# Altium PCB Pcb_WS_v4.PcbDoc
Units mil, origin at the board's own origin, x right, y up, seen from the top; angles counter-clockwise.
Board outline 3937.01 x 3937.01 mil, 2 copper layers (Top Layer, Bottom Layer); 75 components, 61 nets, 248 pads, 32 vias.
Unrouted connection lines stored in the file: 190.
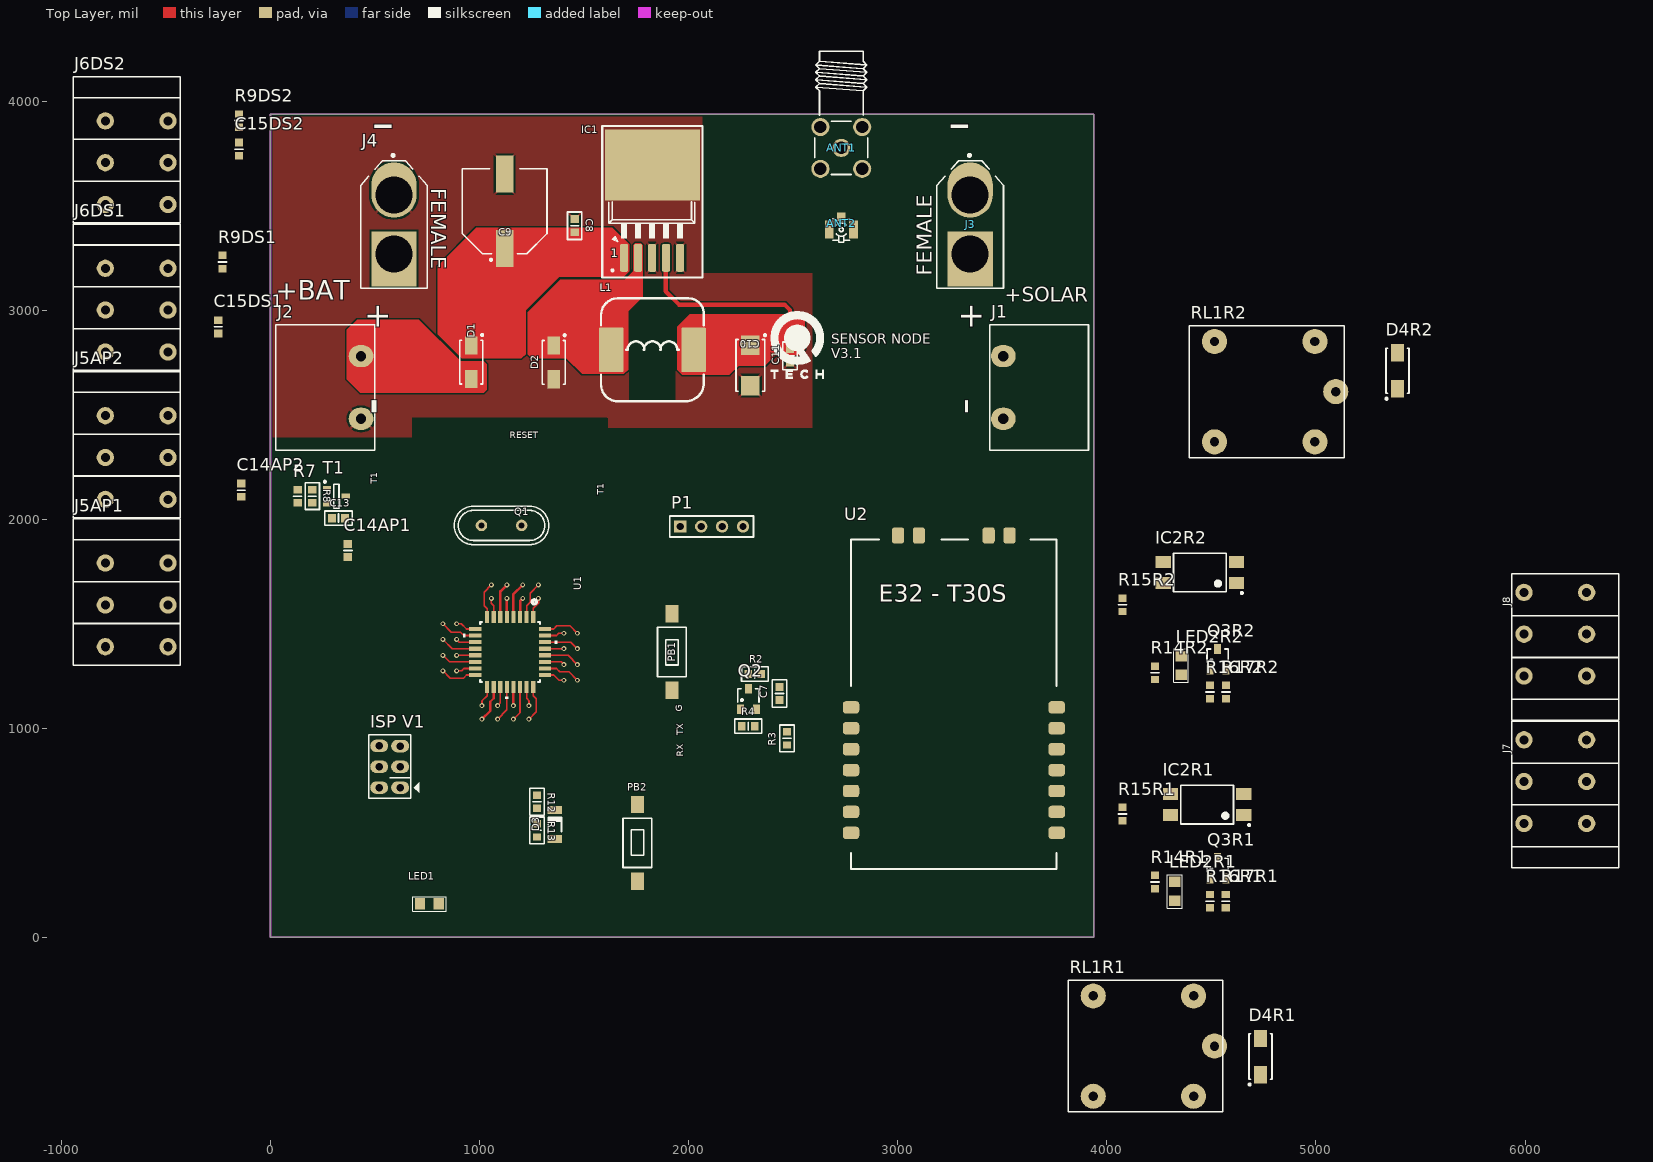
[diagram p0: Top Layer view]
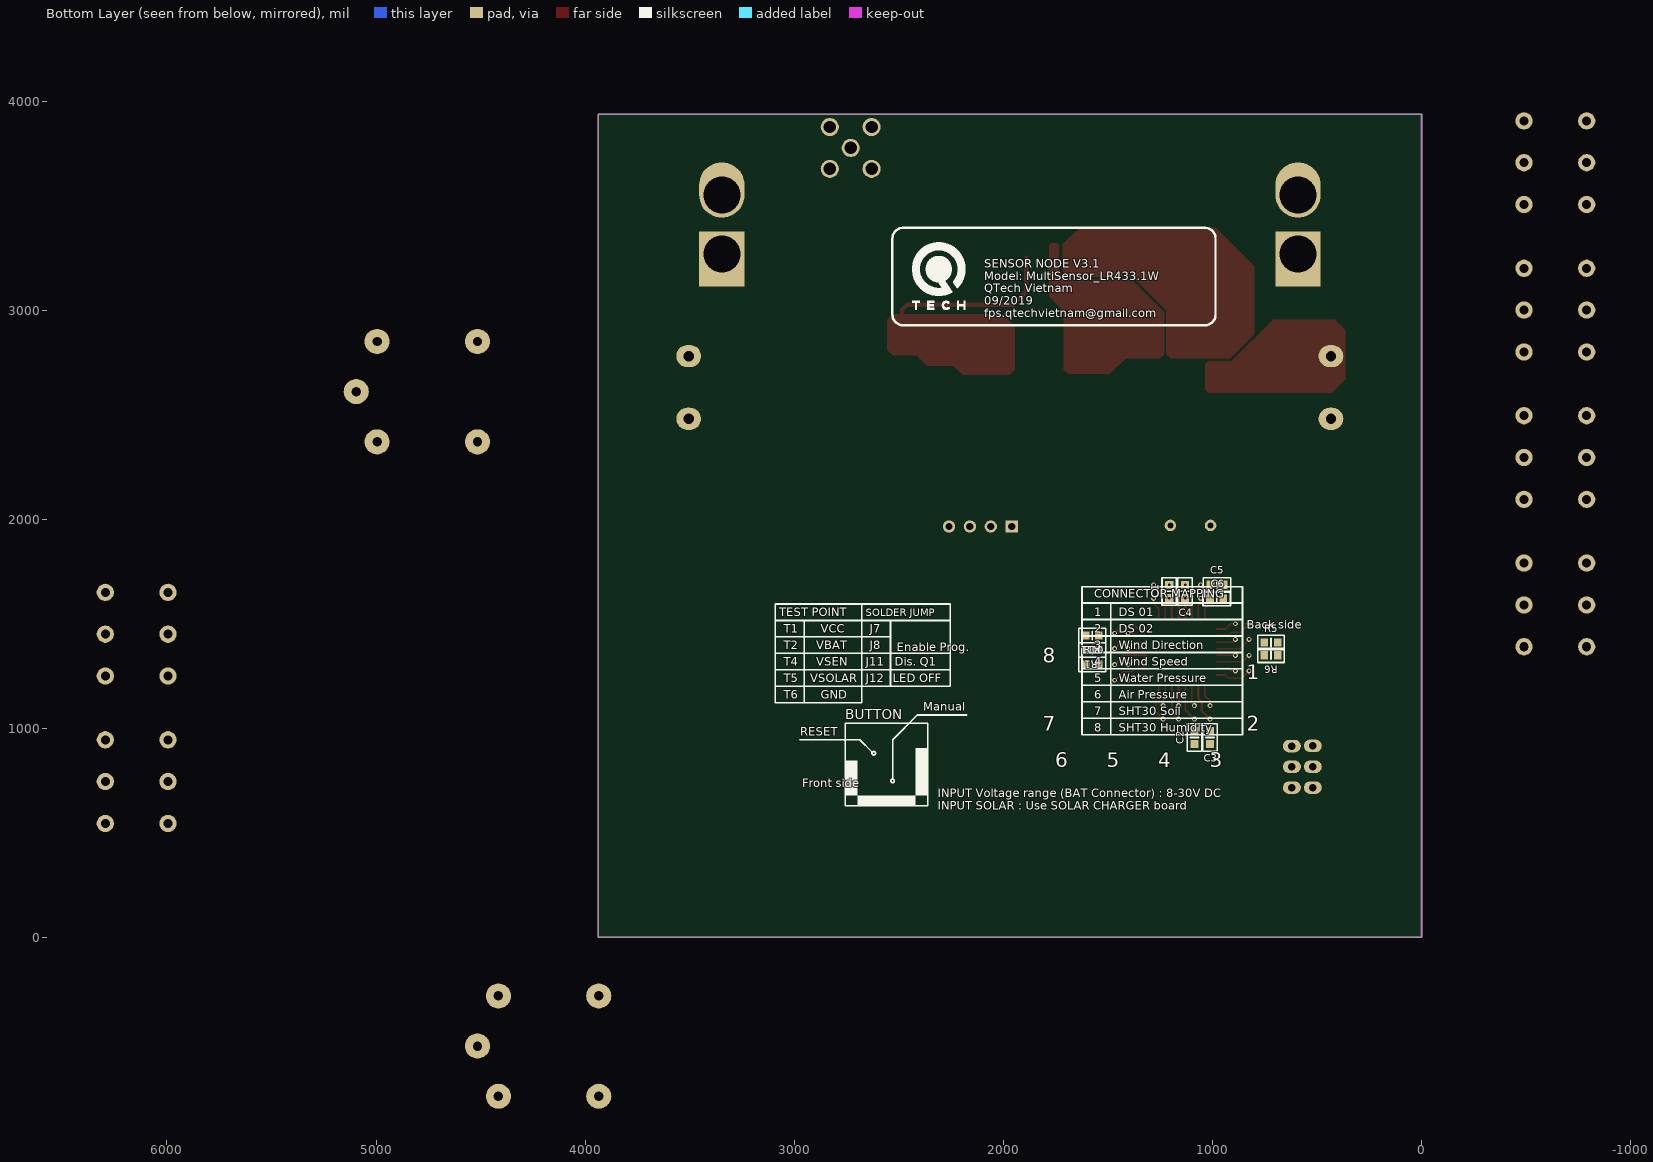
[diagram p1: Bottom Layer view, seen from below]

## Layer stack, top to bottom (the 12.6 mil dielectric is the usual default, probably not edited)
Top Solder: solder mask 0.4, Solder Resist, Dk 3.5
Top Layer: signal copper 1.4
Dielectric 1: dielectric 12.6, FR-4, Dk 4.8
Bottom Layer: signal copper 1.4
Bottom Solder: solder mask 0.4, Solder Resist, Dk 3.5

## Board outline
0,0 0,3937.01 3937.01,3937.01 3937.01,0

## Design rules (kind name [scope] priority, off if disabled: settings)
Clearance [All] p1: gap=7 ignorepadtopadclearanceinfootprint=FALSE
ComponentClearance KF-conn_Clearance [InComponentClass('KF_conn') vs InComponentClass('KF_conn')] p1: gap=5 collisioncheckmode=3 verticalgap=0 showdistances=FALSE
ComponentClearance HS_Comp_Clearance [InComponentClass('HS_Comp')] p2: gap=175 collisioncheckmode=3 verticalgap=100 showdistances=FALSE
ComponentClearance IC_Comp_Clearance [InComponentClass('IC_Comp') And OnLayer('Top Layer') vs IsComponent And OnLayer('Top Layer')] p3: gap=150 collisioncheckmode=3 verticalgap=100 showdistances=FALSE
ComponentClearance conn-th_Clearance [InComponentClass('conn-th')] p4: gap=150 collisioncheckmode=3 verticalgap=250 showdistances=FALSE
ComponentClearance chip-ge_Clearance [InComponentClass('chip-ge')] p5: gap=100 collisioncheckmode=3 verticalgap=50 showdistances=FALSE
ComponentClearance chip-0603_Clearance [InComponentClass('chip-0603')] p6: gap=15 collisioncheckmode=3 verticalgap=10 showdistances=FALSE
PolygonConnect [All] p1: thpad.connectstyle=Relief thpad.reliefconductorwidth=13.78 thpad.reliefentries=4 thpad.polygonreliefangle="45 Angle" thpad.airgapwidth=10 smdpad.connectstyle=Relief smdpad.reliefconductorwidth=11.81 smdpad.reliefentries=4 smdpad.polygonreliefangle="45 Angle" smdpad.airgapwidth=10 via.connectstyle=Direct via.reliefconductorwidth=10 via.reliefentries=4 via.polygonreliefangle="90 Angle" via.airgapwidth=10
RoutingVias [All] p1: holewidth=11.81 width=23.62 viastyle="Through Hole" minholewidth=11.81 minwidth=23.62 maxholewidth=11.81 maxwidth=23.62
ShortCircuit [All] p1: allowed=TRUE
SolderMaskExpansion [All] p1: expansion=4 istentingtop=FALSE
Width [All] p1: maxlimit=196.85 minlimit=8 preferedwidth=8
28 further rules are at their usual default settings.

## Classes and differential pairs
component class KF_conn: J5AP1 J5AP2 J6DS1 J6DS2 J7 J8
component class HS_Comp: ANT1 ANT2 Q1
component class IC_Comp: IC1 IC2R1 IC2R2 L1 U1 U2
component class chip-ge: C9 C10 D1 D2 D4R1 D4R2
component class conn-th: "ISP V1" J1 J2 J3 J4 J5AP1 J5AP2 J6DS1 J6DS2 J7 J8 P1 PB1 PB2 RL1R2
component class chip-0603: C1 C2 C3 C4 C5 C6 C7 C8 C11 C13 C14AP1 C14AP2 C15DS1 C15DS2 D3 LED1 LED2R1 LED2R2 Q2 Q3R1 Q3R2 R1 R2 R3 R4 R5 R6 R7 R8 R9DS1 R9DS2 R10 R11 R12 R13 R14R1 R14R2 R15R1 R15R2 R16R1 R16R2 R17R1 R17R2 T1
channel class Sensor_DS18b20_1Wire: DS1 DS2
channel class Sensor_AirPressure_1Wire: AP1 AP2
channel class Relay: R1 R2
component class Top_Level: D3 J7 J8 LED1 P1 PB2 R10 R11 R12 R13
component class R2: D4R2 IC2R2 LED2R2 Q3R2 R14R2 R15R2 R16R2 R17R2 RL1R2
component class R1: D4R1 IC2R1 LED2R1 Q3R1 R14R1 R15R1 R16R1 R17R1
component class Main: C1 C2 C3 C4 C5 C6 "ISP V1" PB1 Q1 R1 U1
component class Lora: ANT1 ANT2 C7 Q2 R2 R3 R4 R5 R6 U2
component class DS2: C15DS2 J6DS2 R9DS2
component class DS1: C15DS1 J6DS1 R9DS1
component class AP2: C14AP2 J5AP2
component class AP1: C14AP1 J5AP1
component class PWR: C8 C9 C10 C11 C13 D1 D2 IC1 J1 J2 J3 J4 L1 R7 R8 T1

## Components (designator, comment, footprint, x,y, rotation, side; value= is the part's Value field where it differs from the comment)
ANT1 "Coax_1Female_1Shield" "HUBER-SUHNER_85 SMA-50-0-101/111 NE" 2729.98,3775.65 r90 top
ANT2 "U.FL" HIROSE_U.FL-R-SMT-1(10) 2729.98,3385 r180 top
C1 "100nF" CAPC1608X87N 1206.61,1654.72 r270 bottom
C2 "100nF" CAPC1608X87N 1086.21,955.57 r90 bottom
C3 "100nF" CAPC1608X87N 1011.21,955.57 r270 bottom
C4 "100nF" CAPC1608X87N 1130.66,1654.72 r270 bottom
C5 "100nF" CAPC1608X87N 978.46,1686.21 r180 bottom value=22pF
C6 "100nF" CAPC1608X87N 979.41,1621.21 r180 bottom value=22pF
C7 "100nF" CAPC1608X87N 2435,1166.5 r270 top
C8 "100nF" CAPC1608X87N 1455,3403.5 r90 top
C9 "470uF" CAPAE1030X1020N 1120,3472.83 r90 top
C10 "100uF" CAPMP6032X280N 2295,2735.24 r270 top
C11 "100nF" CAPC1608X87N 2485,2781.5 r270 top
C13 "100nF" CAPC1608X87N 325,2005.04 r180 top
C14AP1 "100nF" CAPC1608X87N 370,1850 r90 top (schematic designator C14)
C14AP2 "100nF" CAPC1608X87N -140,2138.5 r90 top (schematic designator C14)
C15DS1 "100nF" CAPC1608X87N -250,2920 r90 top (schematic designator C15)
C15DS2 "100nF" CAPC1608X87N -150,3770 r90 top (schematic designator C15)
D1 "SS16" DIOM5127X229N 960,2750.71 r270 top
D2 "SS16" DIOM5127X229N 1355,2750 r270 top
D3 "BZV55-B5V1" DIOMELF3515N 1360,540 r270 top
D4R1 "BZG03C220" DIOM5326X230N 4735,-570 r90 top (schematic designator D4)
D4R2 "BZG03C220" DIOM5326X230N 5390,2710 r90 top (schematic designator D4)
IC1 "LM2596" TO263-5 1691.14,3250 r0 top
IC2R1 "SFH6156-4" SOIC254P977X406-4N 4480,635 r180 top (schematic designator IC2)
IC2R2 "SFH6156-4" SOIC254P977X406-4N 4445,1745 r180 top (schematic designator IC2)
"ISP V1" "Connector 3x2" JP3x2 570,816 r90 top
J1 "CON KF7.62-2P" "CON KF7.62-2P" 3505,2630 r270 top
J2 "CON KF7.62-2P" "CON KF7.62-2P" 433.07,2630 r90 top
J3 "XT60-FM" XT60-FM 3346.46,3409.45 r270 top locked
J4 "XT60-FM" XT60-FM 590.55,3409.45 r270 top locked
J5AP1 "KF142V-3P" "CON KF142V-3P-5.08" -490,1390 r90 top (schematic designator J5)
J5AP2 "KF142V-3P" "CON KF142V-3P-5.08" -490,2095 r90 top (schematic designator J5)
J6DS1 "KF142V-3P" "CON KF142V-3P-5.08" -490,2800 r90 top (schematic designator J6)
J6DS2 "KF142V-3P" "CON KF142V-3P-5.08" -490,3505 r90 top (schematic designator J6)
J7 "KF142V-3P" "CON KF142V-3P-5.08" 5995,945 r270 top
J8 "KF142V-3P" "CON KF142V-3P-5.08" 5995,1650 r270 top
L1 "33uH" L_SMD 1630,2810 r90 top
LED1 "LED" L-0805 760,160 r180 top value="LED 3 ly Single Colour"
LED2R1 "LED" L-0805 4325,220 r90 top value="LED 3 ly Single Colour" (schematic designator LED2)
LED2R2 "LED" L-0805 4355,1300 r90 top value="LED 3 ly Single Colour" (schematic designator LED2)
P1 "Header 4" HDR1X4 1960,1965 r0 top
PB1 "Push Button" PB_TYCO_FSMSM 1920,1365 r270 top
PB2 "Push Button" PB_TYCO_FSMSM 1755,451.93 r90 top
Q1 "20MHz" XTAL_HC-49/U 1105,1970 r0 top
Q2 "C1815" SOT23-3 2285,1140 r0 top
Q3R1 "C1815" SOT23-3 4530,330 r0 top (schematic designator Q3)
Q3R2 "C1815" SOT23-3 4530,1330 r0 top (schematic designator Q3)
R1 "10k" RESC1608X55N 1575,1375 r180 bottom
R2 "10k" RESC1608X55N 2316.5,1260 r0 top value=4k7
R3 "10k" RESC1608X55N 2470,951.5 r90 top value=1k
R4 "10k" RESC1608X55N 2285,1010 r180 top value=1k
R5 "4k7" RESC1608X55N 720,1410 r180 bottom value=10k
R6 "4k7" RESC1608X55N 720,1349.06 r180 bottom value=10k
R7 "1k" RESC1608X55N 130,2110 r90 top
R8 "10k" RESC1608X55N 200,2110 r90 top
R9DS1 "4k7" RESC1608X55N -230,3230 r90 top (schematic designator R9)
R9DS2 "4k7" RESC1608X55N -150,3906.5 r90 top (schematic designator R9)
R10 "10k" RESC1608X55N 1575,1304.61 r0 bottom value=200
R11 "10k" RESC1608X55N 1575,1443.54 r180 bottom
R12 "10k" RESC1608X55N 1275,648.5 r270 top value=2M
R13 "10k" RESC1608X55N 1275,511.5 r270 top value=1M
R14R1 "1k" RESC1608X55N 4230,265 r90 top value=200 (schematic designator R14)
R14R2 "1k" RESC1608X55N 4230,1265 r90 top value=200 (schematic designator R14)
R15R1 "1k" RESC1608X55N 4075,590 r270 top (schematic designator R15)
R15R2 "1k" RESC1608X55N 4075,1590 r270 top (schematic designator R15)
R16R1 "1k" RESC1608X55N 4493,173.5 r90 top value=200 (schematic designator R16)
R16R2 "1k" RESC1608X55N 4493,1173.5 r90 top value=200 (schematic designator R16)
R17R1 "10k" RESC1608X55N 4568.8,173.5 r270 top (schematic designator R17)
R17R2 "10k" RESC1608X55N 4570.2,1173.5 r90 top (schematic designator R17)
RL1R1 "Relay 10A/12V" RL_SPDT_10A 4515,-520 r180 top value="Relay SPDT, 10A, 12V" (schematic designator RL1)
RL1R2 "Relay 10A/12V" RL_SPDT_10A 5095,2610 r180 top value="Relay SPDT, 10A, 12V" (schematic designator RL1)
T1 "BSH203" SOT95P230X110-3N 315,2110 r0 top
U1 "ATmega328-AU" 32A_ATM-M 1146.41,1364.8 r270 top locked
U2 "E32-T30S" E32-T30S 3760,1902.36 r180 top

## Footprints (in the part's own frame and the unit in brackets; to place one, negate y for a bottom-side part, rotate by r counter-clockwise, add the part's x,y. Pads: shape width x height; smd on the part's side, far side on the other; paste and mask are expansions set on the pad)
32A_ATM-M [mil]
  rect 58x20 smd paste+0 mask+5: 1(-167,110.24) 2(-167,78.74) 3(-167,47.24) 4(-167,15.75) 5(-167,-15.75) 6(-167,-47.24) 7(-167,-78.74) 8(-167,-110.24) 17(167,-110.24) 18(167,-78.74) 19(167,-47.24) 20(167,-15.75) 21(167,15.75) 22(167,47.24) 23(167,78.74) 24(167,110.24)
  rect 20x58 smd paste+0 mask+5: 9(-110.24,-167) 10(-78.74,-167) 11(-47.24,-167) 12(-15.75,-167) 13(15.75,-167) 14(47.24,-167) 15(78.74,-167) 16(110.24,-167) 25(110.24,167) 26(78.74,167) 27(47.24,167) 28(15.75,167) 29(-15.75,167) 30(-47.24,167) 31(-78.74,167) 32(-110.24,167)
  silkscreen extent -250,-224 224,224, body extent -182,-182 182,182, height 47
CAPAE1030X1020N [mm] "Capacitor, Aluminium Electrolytric, 10.3mm L X 10.3mm W X 10.2mm H, IPC Medium Density"
  rect 4.5x2.1 smd: 1(-4.5,0) 2(4.5,0)
  silkscreen extent -6.02,-5.15 5.15,5.15, body extent -6,-5.25 6,5.25, height 10.2
CAPC1608X87N [mm] "Chip Capacitor, Body 1.6x0.8mm IPC Medium Density"
  rect 0.95x1 smd: 1(-0.8,0) 2(0.8,0)
  silkscreen extent -1.68,-0.87 1.68,0.87, body extent -0.87,-0.47 0.88,0.48, height 0.87
CAPMP6032X280N [mm] "Capacitor, Polarized, Molded  Body 6.0x3.2mm, IPC Medium Density"
  rect 2.35x2.25 smd: 1(-2.45,0) 2(2.45,0)
  silkscreen extent -3.8,-1.75 3.15,1.9, body extent -3.15,-1.75 3.15,1.75, height 2.8
"CON KF7.62-2P" [mm]
  oval 2.7x3 hole 1.26: 1(-3.81,0) 2(3.81,0)
  silkscreen extent -7.62,-1.65 7.62,10.35, body extent -7.62,-1.65 7.62,10.35, height 12.4
"CON KF142V-3P-5.08" [mm]
  round 2.1 hole 1.1: 1(0,7.62) 1(0,0) 2(5.08,7.62) 2(5.08,0) 3(10.16,0) 3(10.16,7.62)
  silkscreen extent -2.25,-1.5 15.53,11.5, body extent -2.14,-1.57 15.54,11.63, height 14.23
DIOM5127X229N [mm] "DO-214-AC/SMA Molded Diode, 2-Leads, Body 5.1x2.7mm, IPC Medium Density"
  rect 2.2x1.55 smd: 1(-2.05,0) 2(2.05,0)
  silkscreen extent -3.42,-1.4 2.65,1.45, body extent -2.67,-1.45 2.68,1.45, height 2.29
DIOM5326X230N [mm] "DO-214-AC/SMA Molded Diode, Body 5.3x2.6mm, IPC Medium Density"
  rect 2.1x1.55 smd: 1(-2.2,0) 2(2.2,0)
  silkscreen extent -3.52,-1.4 2.75,1.45, body extent -2.75,-1.4 2.75,1.4, height 2.3
DIOMELF3515N [mm] "SOD80C, MELF Diode, 2-Leads, Body 3.5x1.5mm, IPC Medium Density"
  rect 1x1.75 smd: 1(-1.75,0) 2(1.75,0)
  silkscreen extent -0.85,-0.8 0.85,0.8, body extent -1.85,-0.8 1.85,0.8, height 1.6
E32-T30S [mm] "Lora-EBYTE-21~30dBm-UART-SX1278-25x40mm"
  rrect50% 2x1.5 smd: 1(0,20.38) 2(0,22.92) 3(0,25.46) 4(0,28) 5(0,30.54) 6(0,33.08) 7(0,35.62) 8(24.98,35.62) 9(24.98,33.08) 10(24.98,30.54) 11(24.98,28) 12(24.98,25.46) 13(24.98,22.92) 14(24.98,20.38)
  rrect50% 1.5x2 smd: 15(19.27,-0.5) 16(16.73,-0.5) 17(8.27,-0.5) 18(5.73,-0.5)
  silkscreen extent 0,0 25,40, body extent 0,0 25,40, height 3.5
HDR1X4 [mm] "Connector; Header; 4 Position"
  rect 1.5x1.5 hole 0.9: 1(0,0)
  round 1.5 hole 0.9: 2(2.54,0) 3(5.08,0) 4(7.62,0)
  silkscreen extent -1.27,-1.27 8.89,1.27
HIROSE_U.FL-R-SMT-1(10) [mm] "Up to 6GHz Ultra Small Surface Mount Male Coaxial Connectors U.FL Series"
  rect 1x1.05 smd: 1(0,-1.525)
  rect 1.05x2.2 smd: 2(-1.475,0) 2(1.475,0)
  silkscreen extent -1,-1.3 1,1.55, body extent -1.5,-1.55 1.5,1.55, height 1.25
"HUBER-SUHNER_85 SMA-50-0-101/111 NE" [mm] "50 Ohm SMA Right Angle PCB Jack"
  round 2.2 hole 1.5: 1(0,0) 2(-2.54,-2.54) 2(-2.54,2.54) 2(2.54,-2.54) 2(2.54,2.54)
  silkscreen extent -3.23,-3.23 11.73,3.23, body extent -3.23,-3.23 11.73,3.23, height 9.6
JP3x2 [mil] "Connector 3x2"
  oval 60x86 hole 36: 1(-100,-50) 2(0,-50) 3(99,-50) 4(-100,50) 5(0,50) 6(100,50)
  silkscreen extent -150,-141 154,100, body extent -150,-100 150,100, height 335
L-0805 [mil] "Compoment SMD 80x50mil"
  rect 50x55 smd: 1(-45,0) 2(45,0)
  silkscreen extent -80,-35 80,35, body extent -50,-20 50,20, height 43
L_SMD [mm]
  rrect10% 5.4x3 smd mask+0.1: 1(0,0) 2(0,-10)
  silkscreen extent -6.25,-11.25 6.25,1.25, body extent -6.25,-11.25 6.25,1.25, height 6.7
PB_TYCO_FSMSM [mm] "Body 3.5x6.0mm, Pushbutton Switch,  TYCO FSMSM Serie"
  rect 2.1x1.6 smd: 1(-4.65,0) 2(4.65,0)
  silkscreen extent -3,-1.75 3,1.75, body extent -5,-1.75 5,1.75, height 4.3
RESC1608X55N [mm] "Chip Resistor, EIA 0603, Metric 1608, Body 1.6x0.8mm, IPC Medium Density"
  rect 0.9x1 smd: 1(-0.8,0) 2(0.8,0)
  silkscreen extent -1.63,-0.87 1.63,0.87, body extent -0.87,-0.47 0.88,0.48, height 0.55
RL_SPDT_10A [mil] "Relay SPDT, 5 pin, 10A,W 650mil, L 800mil, H 800mil"
  round 120 hole 45: 1(0,0) 2(580,240) 3(580,-240) 4(100,-240) 5(100,240)
  silkscreen extent -40,-315 700,315
SOIC254P977X406-4N [mm] "SOIC, 2.54mm pitch; 4 pin, 6.65mm W X 4.69mm L, IPC Medium Density"
  rect 1.85x1.45 smd: 1(-4.45,1.27) 2(-4.45,-1.27) 3(4.45,-1.27) 4(4.45,1.27)
  silkscreen extent -5.23,-2.35 3.2,2.62, body extent -5.01,-2.41 5.02,2.42, height 4.06
SOT23-3 [mm] "SOT 23"
  rect 0.85x1.2 smd: 1(-0.94,-1.245) 2(0.985,-1.25) 3(0.005,1.25)
  silkscreen extent -1.29,-0.38 1.31,1.25, body extent -1.5,-1.5 1.52,1.5, height 1.27
SOT95P230X110-3N [mm] "SOT23, 3 pin, Pitch 0.95mm - 1.3mm W X 2.9mm L X 1.1mm H, IPC Medium Density"
  rect 1x0.6 smd: 1(-1.15,0.95) 2(-1.15,-0.95) 3(1.15,0)
  silkscreen extent -1.52,-1.45 0.33,1.87, body extent -1.17,-1.5 1.33,1.5, height 1.1
TO263-5 [mm]
  rrect50% 1x3.4 smd: 1(0,0) 2(1.7,0) 4(5.1,0) 5(6.8,0)
  rrect50% 1x3.4 smd mask+0: 3(3.4,0)
  rect 11.5x8.634 smd: 6(3.45,11.302)
  silkscreen extent -2.66,-2.38 9.54,16.02, body extent -1.71,-0.87 8.45,13.77, height 4.57
XT60-FM [mm]
  oval 6.716x5.516 hole 4.5 copper offset -0.6,0: 1(-3.6,0)
  rect 6.716x5.516 hole 4.5 copper offset 0.6,0: 2(3.6,0)
  silkscreen extent -8.55,-4.05 7.75,4.05, body extent -7.81,-4.07 8.12,4.06, height 15.5
XTAL_HC-49/U [mm] "HC-49/U Leaded Cristal, Body 11.05x4.8mm; Pitch 4.88mm"
  round 1.4 hole 0.7: 1(-2.44,0) 2(2.44,0)
  silkscreen extent -5.75,-2.33 5.75,2.33, body extent -5.75,-2.33 5.75,2.33, height 3.5

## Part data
ANT1: library part HUBER-SUHNER_85_SMA-50-0-101/111_NE, Manufacturer=HUBER+SUHNER, Manufacturer Part Number=85_SMA-50-0-101/111_NE
ANT2: library part HIROSE_U.FL-R-SMT-1(10), Manufacturer="HIROSE (HRS)", Manufacturer Part Number=U.FL-R-SMT-1(10)
C1 C2 C3 C4 C7 C8 C11 C13 C14AP1 C14AP2 C15DS1 C15DS2: library part CC0603_100NF_50V_10%_X7R, "Non-polarised capacitor", Case=0603, Manufacturer=GENERIC, Manufacturer1 ComponentHeight=0.87mm, Manufacturer1 Example=PHYCOMP, Manufacturer1 Part Number=223858615649, Tolerance=±10%, Voltage=50V
C5 C6: library part CC0603_22PF_50V_5%_NP0, "Non-polarised capacitor", Case=0603, Manufacturer=GENERIC, Manufacturer1 ComponentHeight=0.87mm, Manufacturer1 Example=PHYCOMP, Manufacturer1 Part Number=223886715229, Tolerance=±5%, Voltage=50V
C9: library part CAE1030-1020_470UF_25V_20%, "Polarised capacitor", Case=G, Manufacturer=GENERIC, Manufacturer1 ComponentHeight=10.2mm, Manufacturer1 Example=PANASONIC, Manufacturer1 Part Number=EEEFK1E471AP, Tolerance=±20%, Voltage=25V
C10: library part CTE6032-28_100UF_6.3V_10%_LESR0075, "Polarised capacitor", Case=C, Manufacturer=GENERIC, Manufacturer1 ComponentHeight=2.8mm, Manufacturer1 Example=AVX, Manufacturer1 Part Number=TPSC107K006R0075, Tolerance=±10%, Voltage=6.3V
D1 D2: "Schottky Diode", Case=DO-214AC, Manufacturer="VISHAY GENERAL SEMICONDUCTOR", Power=1A, Voltage=60V
D3: "Zener Diode", Case=SOD-80C, Manufacturer="NXP SEMICONDUCTORS", Power=500mW, Voltage=5V1
D4R1 D4R2: "Zener Diode", Case=DO-214AC, Manufacturer="VISHAY SEMICONDUCTOR", Power=1.25W, Voltage=220V
IC1: library part LM2596-5V
IC2R1 IC2R2: "Single Optocoupler", Case=SOIC4, Manufacturer="VISHAY SEMICONDUCTORS"
"ISP V1": library part JP3x2
J3 J4: Package="Package Analog Devices"
J5AP1 J5AP2 J6DS1 J6DS2 J7 J8: library part "CON KF142V-3P-5.08", "CON KF142V-3P-5.08"
L1: library part "L_SMD 33uH"
LED1 LED2R1 LED2R2: "LED Single colour Green and Red"
P1: "Header, 4-Pin"
PB1 PB2: "Push-Button Switch SPDT", Manufacturer="TYCO ELECTRONICS", Manufacturer Part Number="FSMSM or 1437566-3", Part Number=PB_TYCO_FSMSM
Q1: library part XTAL_20MHZ_AEL_HC-49/U, "Quartz Crystal", Manufacturer="AEL CRYSTALS", Manufacturer Part Number=X20M000000L010
Q2 Q3R1 Q3R2: library part 2SC1815, PSpiceTemplate="Q^@REFDES %c %b %e @MODEL"
R1 R5 R6 R8 R11 R17R1 R17R2: library part R0603_10K_1%_0.1W_100PPM, "Resistor - 1%", Case=0603, Manufacturer=GENERIC, Manufacturer1 ComponentHeight=0.55mm, Manufacturer1 Example="NIC COMPONENT", Manufacturer1 Part Number=NRC06F1002TRF, Power=0.1W, Tolerance=±1%
R2 R9DS1 R9DS2: library part R0603_4K7_1%_0.1W_100PPM, "Resistor - 1%", Case=0603, Manufacturer=GENERIC, Manufacturer1 ComponentHeight=0.55mm, Manufacturer1 Example="NIC COMPONENT", Manufacturer1 Part Number=NRC06F4701TRF, Power=0.1W, Tolerance=±1%
R3 R4 R7 R15R1 R15R2: library part R0603_1K_1%_0.1W_100PPM, "Resistor - 1%", Case=0603, Manufacturer=GENERIC, Manufacturer1 ComponentHeight=0.55mm, Manufacturer1 Example="NIC COMPONENT", Manufacturer1 Part Number=NRC06F1001TRF, Power=0.1W, Tolerance=±1%
R10 R14R1 R14R2 R16R1 R16R2: library part R0603_200R_1%_0.1W_100PPM, "Resistor - 1%", Case=0603, Manufacturer=GENERIC, Manufacturer1 ComponentHeight=0.55mm, Manufacturer1 Example="NIC COMPONENT", Manufacturer1 Part Number=NRC06F2000TRF, Power=0.1W, Tolerance=±1%
R12: library part R0603_2M_1%_0.1W_100PPM, "Resistor - 1%", Case=0603, Manufacturer=GENERIC, Manufacturer1 ComponentHeight=0.55mm, Manufacturer1 Example="NIC COMPONENT", Manufacturer1 Part Number=NRC06F2004TRF, Power=0.1W, Tolerance=±1%
R13: library part R0603_1M_1%_0.1W_100PPM, "Resistor - 1%", Case=0603, Manufacturer=GENERIC, Manufacturer1 ComponentHeight=0.55mm, Manufacturer1 Example="NIC COMPONENT", Manufacturer1 Part Number=NRC06F1004TRF, Power=0.1W, Tolerance=±1%
RL1R1 RL1R2: library part "Relay 1", "Relay SPDT,10A - 12VDC 5 Pin"
T1: "P-CHANNEL MOSFET WITH DIODE", Case=SOT23-3, Manufacturer="NXP SEMICONDUCTORS"
U1: "8-bit AVR Microcontroller, 32KB Flash, 1KB EEPROM, 2KB SRAM, 32-pin TQFP, Industrial Grade (-40°C to 85°C)", Supplier Part Number 1=ATMEGA328-AU-ND
U2: library part E32-433T30S, "Lora Ebyte E32-T30S Module"

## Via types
v1: diameter 23.62, hole 11.81, Top Layer to Bottom Layer, 32 vias

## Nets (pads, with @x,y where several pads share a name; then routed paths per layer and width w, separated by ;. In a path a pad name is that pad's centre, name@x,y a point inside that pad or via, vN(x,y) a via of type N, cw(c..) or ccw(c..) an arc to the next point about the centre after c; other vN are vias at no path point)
ANT_M: U2.18
ANT_M1: ANT1.1 ANT2.1
AREF: C2.2 U1.20 | length 172.8
  Top Layer w8: v1(1086.21,1043.39) 1130.66,1087.84 U1.20
AUX: U1.2 U2.5 | length 177.8
  Top Layer w8: U1.2 1225.15,1586.13 1241.61,1602.59 1241.61,1646.21 v1(1281.61,1686.21)
BAT-VSEN: C8.1 C9.1 D1.1 IC1.1 R12.1
BAT-VSEN-Q: D3.1 R12.2 R13.1 U1.23 | length 94
  Top Layer w8: U1.23 1225.15,1143.48 1236.21,1132.41 v1(1236.21,1108.39)
CLOSE1: J7.3 RL1R1.2
CLOSE2: J8.3 RL1R2.2
COM1: J7.2 RL1R1.1
COM2: J8.2 RL1R2.1
DATA-AP1: J5AP1.2 U1.24 | length 174.9
  Top Layer w8: v1(1236.21,1043.39) 1271.21,1078.39 1271.21,1141.39 1256.65,1155.96 U1.24
DATA-AP2: J5AP2.2 U1.25 | length 99.7
  Top Layer w8: U1.25 1355.25,1254.57 1380.21,1229.61 v1(1402.82,1229.61)
DATA-DS1: J6DS1.2 R9DS1.1 U1.1 | length 99.7
  Top Layer w8: U1.1 1256.65,1573.65 1281.61,1598.61 v1(1281.61,1621.21)
DATA-DS2: J6DS2.2 R9DS2.1 U1.9 | length 99.7
  Top Layer w8: v1(890,1500) 912.61,1500 937.57,1475.04 U1.9
GND: "ISP V1.5" ANT1.2 ANT2.2 C1.2 C2.1 C3.2 C4.2 C5.2 C6.2 C7.2 C8.2 C9.2 C10.2 C11.2 C13.2 C14AP1.1 C14AP2.1 C15DS1.1 C15DS2.1 D2.2 D3.2 IC1.3 IC1.5 IC1.6 IC2R1.2 IC2R2.2 J2.1 J4.1 J5AP1.3 J5AP2.3 J6DS1.3 J6DS2.3 LED1.2 P1.4 PB1.2 PB2.2 Q2.2 Q3R1.2 Q3R2.2 R4.1 R5.2 R6.2 R7.1 R13.2 R17R1.1 R17R2.1 U1.3 U1.5 U1.21 U2.7 U2.9 U2.15 U2.16 U2.17 | length 273.6
  Top Layer w12: U1.5 v1(1130.66,1621.21) ; v1(1162.16,1108.39) U1.21 ; U1.3 1193.65,1608.26 v1(1206.61,1621.21)
GND-SOLAR: J1.2 J3.1
LED: R10.1 U1.28 | length 172.8
  Top Layer w8: U1.28 1423.37,1349.06 v1(1467.82,1304.61)
M0: U1.11 U2.1 | length 94.8
  Top Layer w8: v1(890,1425) 902.95,1412.05 U1.11
M1: U1.12 U2.2 | length 172.8
  Top Layer w8: v1(825,1425) 869.45,1380.55 U1.12
MISO: "ISP V1.2" U1.16 | length 174.9
  Top Layer w8: v1(825,1275) 860,1240 923,1240 937.57,1254.57 U1.16
MOSI: "ISP V1.3" U1.15 | length 94
  Top Layer w8: v1(890,1275) 914.02,1275 925.08,1286.06 U1.15
NetD2_1: D2.1 IC1.2 L1.1
NetD4R1_2: D4R1.2 LED2R1.2 Q3R1.3 RL1R1.4
NetD4R2_2: D4R2.2 LED2R2.2 Q3R2.3 RL1R2.4
NetIC2R1_1: IC2R1.1 R15R1.2
NetIC2R2_1: IC2R2.1 R15R2.2
NetLED1_1: LED1.1 R10.2
NetLED2R1_1: LED2R1.1 R14R1.2
NetLED2R2_1: LED2R2.1 R14R2.2
NetQ2_1: Q2.1 R3.2
NetQ3R1_1: Q3R1.1 R16R1.2
NetQ3R2_1: Q3R2.1 R16R2.2
NetR7_2: R7.2 R8.2 T1.1
NetU1_19: U1.19 | length 94.8
  Top Layer w8: v1(1086.21,1108.39) 1099.17,1121.35 U1.19
NetU1_22: U1.22 | length 167.5
  Top Layer w8: v1(1162.16,1043.39) 1193.65,1074.89 U1.22
NetU2_10: U2.10
NetU2_11: U2.11
NetU2_12: U2.12
NetU2_13: U2.13
NetU2_14: U2.14
OPEN1: J7.1 RL1R1.3
OPEN2: J8.1 RL1R2.3
P5V-Main: "ISP V1.6" C1.1 C3.1 C4.1 C7.1 C10.1 C11.1 D4R1.1 D4R2.1 IC1.4 IC2R1.4 IC2R2.4 L1.2 P1.1 R1.1 R2.2 R8.1 R11.1 R14R1.1 R14R2.1 RL1R1.5 RL1R2.5 T1.2 U1.4 U1.6 U1.18 U2.6 | length 1497.4
  Top Layer w12: v1(1011.21,1043.39) 1051.21,1083.39 1051.21,1127.02 1067.67,1143.48 U1.18 ; U1.6 1099.17,1654.72 v1(1130.66,1686.21) ; U1.4 1162.16,1641.76 v1(1206.61,1686.21)
  Top Layer w20: IC1.4@1890,3250 1890,3090 1954.14,3025.86 2459.14,3025.86 2485,3000 C11.1
P5V-SEN: C13.1 C14AP1.2 C14AP2.2 C15DS1.2 C15DS2.2 J5AP1.1 J5AP2.1 J6DS1.1 J6DS2.1 R9DS1.2 R9DS2.2 T1.3
P12V-BAT: D1.2 J2.2 J4.2
P16V-SOLAR: J1.1 J3.2
RESET-E32: R3.1 R4.2 U1.10 | length 177.8
  Top Layer w8: v1(825,1500) 865,1460 908.62,1460 925.08,1443.54 U1.10
RL-CTL1: R15R1.1 U1.26 | length 177.8
  Top Layer w8: U1.26 1367.74,1286.06 1384.19,1269.61 1427.82,1269.61 v1(1467.82,1229.61)
RL-CTL2: R15R2.1 U1.27 | length 94.8
  Top Layer w8: U1.27 1389.87,1317.56 v1(1402.82,1304.61)
RL-CTR1: IC2R1.3 R16R1.1 R17R1.2
RL-CTR2: IC2R2.3 R16R2.1 R17R2.2
RST-E32: Q2.3 R2.1 U2.8
RST_MCU: "ISP V1.4" PB1.1 R1.2 U1.29 | length 89.4
  Top Layer w8: U1.29 v1(1402.82,1380.55)
RXD-E32: R6.1 U1.13 U2.3 | length 89.4
  Top Layer w8: v1(890,1349.06) U1.13
RXM: P1.3 U1.30 | length 167.5
  Top Layer w8: U1.30 1436.32,1412.05 v1(1467.82,1380.55)
SCK: "ISP V1.1" U1.17 | length 99.7
  Top Layer w8: v1(1011.21,1108.39) 1011.21,1131 1036.17,1155.96 U1.17
TXD-E32: R5.1 U1.14 U2.4 | length 167.5
  Top Layer w8: v1(825,1349.06) 856.5,1317.56 U1.14
TXM: P1.2 U1.31 | length 94
  Top Layer w8: U1.31 1367.74,1443.54 1378.8,1454.61 v1(1402.82,1454.61)
WAKE: PB2.1 R11.2 U1.32 | length 174.9
  Top Layer w8: U1.32 1355.25,1475.04 1369.82,1489.61 1432.82,1489.61 v1(1467.82,1454.61)
XTAL1: C6.1 Q1.1 U1.7 | length 94
  Top Layer w8: v1(1056.61,1621.21) 1056.61,1597.2 1067.67,1586.13 U1.7
XTAL2: C5.1 Q1.2 U1.8 | length 174.9
  Top Layer w8: U1.8 1036.17,1571.57 1021.61,1586.13 1021.61,1651.21 v1(1056.61,1686.21)

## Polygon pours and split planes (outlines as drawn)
GND on Top Layer "GND_L01_P027" (solid, remove dead copper, pour order 27): 0.04,2391.99 0.04,3936.99 2065.04,3936.99 2065.04,3176.99 2590.04,3176.99 2590.04,2436.99 1610.04,2436.99 1610.04,2486.99 675.04,2486.99 675.04,2391.99
no net on Top Layer "AutoNaming" (solid, pour order 26): 0,0
no net on Top Layer "AutoNaming" (solid, pour order 22): 0,0
no net on Top Layer "Top Layer-No Net" (solid, pour order 14): 1502.91,3276.41

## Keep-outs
Keep-Out Layer:
  the board outline again, w7.87

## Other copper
Top Layer:
  region net P5V-Main: 1945,2920 2005,2980 2530,2980 2555,2955 2555,2810 2530,2785 2415,2785 2365,2735 2240,2735 2195,2690 1970,2690 1945,2715
  region: 340,2910
  region net P12V-BAT: 365,2670 430,2605 1020,2605 1035,2620 1035,2740 1020,2755 910,2755 710,2955 415,2955 365,2905
  region net BAT-VSEN: 915,2770 800,2885 800,3210 985,3395 1635,3395 1715,3315 1715,3185 1690,3160 1380,3160 1220,3000 1220,2790 1200,2770
  region net NetD2_1: 1735,3185 1695,3145 1385,3145 1230,2990 1230,2790 1250,2770 1415,2770 1490,2695 1690,2695 1710,2715 1710,2995 1780,3065 1780,3310 1770,3320 1745,3320 1735,3310
  region: 1965,2640
  pour cut-out: 1787.5,3150 1882.5,3150 1882.5,3135 1787.5,3135
  pour cut-out: 3949.69,1440.41
  pour cut-out: 3949.69,1440.41
  region: 991.15,955.57
Multi-Layer:
  pour cut-out: 1715,3000 1715,2570 1935,2570 1935,3000
  pour cut-out: 0,2389 681.15,2389 681.15,2484 1615.34,2484 1615.34,2436.76 717.39,2436.76 717.39,2351 0,2351

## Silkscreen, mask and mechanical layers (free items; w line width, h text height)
Top Overlay:
  drawing of 802 lines, arcs and shapes, not listed
  text "-" at 482.28,3720.47 h393.7
  text "-" at 3238.19,3720.47 h393.7
  text "FEMALE" at 767.72,3582.48 h70.87 r270
  text "FEMALE" at 3162.72,3165.48 h70.87 r90
  text "+BAT" at 26,3018 h157.48
  text "+SOLAR" at 3511,3015 h118.11
  text "+" at 600.39,2904.11 h196.85 r90
  text "+" at 3438.98,2903.54 h196.85 r90
  text "SENSOR NODE / V3.1" at 2682.41,2769.24 h47.24
  text "-" at 600.39,2500 h275.59 r90
  text "-" at 610.24,2500 h275.59 r90
  text "-" at 3438.98,2500 h275.59 r90
  text "RESET" at 1145.39,2388.26 h31.5
  text "T1" at 511.83,2168.48 h31.5 r90
  text "T1" at 1594,2116.39 h31.5 r90
  text "G" at 1970.39,1078.39 h31.5 r90
  text "TX" at 1973.39,967.39 h31.5 r90
  text "RX" at 1973.39,863.39 h31.5 r90
Bottom Overlay:
  drawing of 873 lines, arcs and shapes, not listed
  text "SENSOR NODE V3.1 / Model: MultiSensor_LR433.1W / QTech Vietnam / 09/2019 / fps.qtechvietnam@gmail.com" at 2092.27,2966.11 h39.37
  text "CONNECTOR MAPPING" at 1565.09,1624.02 h39.37
  text "DS 01" at 1446.98,1535.43 h39.37
  text "1" at 1564.96,1535.43 h39.37
  text "SOLDER JUMP" at 2657.48,1535.43 h35.43
  text "TEST POINT" at 3070.87,1535.43 h39.37
  text "Back side" at 836.61,1476.38 h39.37
  text "DS 02" at 1446.98,1456.69 h39.37
  text "2" at 1564.96,1456.69 h39.37
  text "J7" at 2637.8,1456.69 h39.37
  text "VCC" at 2874.02,1456.69 h39.37
  text "T1" at 3051.18,1456.69 h39.37
  text "Wind Direction" at 1446.98,1377.95 h39.37
  text "3" at 1565.09,1377.95 h39.37
  text "J8" at 2637.8,1377.95 h39.37
  text "VBAT" at 2893.7,1377.95 h39.37
  text "T2" at 3051.18,1377.95 h39.37
  text "Enable Prog." at 2509.84,1368.11 h39.37
  text "Wind Speed" at 1446.98,1299.21 h39.37
  text "4" at 1565.09,1299.21 h39.37
  text "Dis. Q1" at 2519.68,1299.21 h39.37
  text "J11" at 2657.48,1299.21 h39.37
  text "VSEN" at 2893.7,1299.21 h39.37
  text "T4" at 3051.18,1299.21 h39.37
  text "8" at 1811.15,1289.37 h118.11
  text "Water Pressure" at 1446.98,1220.47 h39.37
  text "5" at 1565.09,1220.47 h39.37
  text "LED OFF" at 2529.53,1220.47 h39.37
  text "J12" at 2657.48,1220.47 h39.37
  text "VSOLAR" at 2923.23,1220.47 h39.37
  text "T5" at 3051.18,1220.47 h39.37
  text "1" at 836.74,1210.63 h118.11
  text "Air Pressure" at 1446.98,1141.73 h39.37
  text "6" at 1565.09,1141.73 h39.37
  text "GND" at 2874.02,1141.73 h39.37
  text "T6" at 3051.18,1141.73 h39.37
  text "Manual" at 2382.02,1083.06 h39.37
  text "SHT30 Soil" at 1446.98,1062.99 h39.37
  text "7" at 1565.09,1062.99 h39.37
  text "BUTTON" at 2755.91,1043.31 h47.24
  text "SHT30 Humidity" at 1446.98,984.25 h39.37
  text "8" at 1565.09,984.25 h39.37
  text "2" at 836.74,964.57 h118.11
  text "7" at 1811.15,964.57 h118.11
  text "RESET" at 2972.44,964.57 h39.37
  text "3" at 1013.91,789.45 h118.11
  text "4" at 1259.97,789.45 h118.11
  text "5" at 1506.03,789.45 h118.11
  text "6" at 1752.09,789.45 h118.11
  text "Front side" at 2962.6,718.5 h39.37
  text "INPUT Voltage range (BAT Connector) : 8-30V DC / INPUT SOLAR : Use SOLAR CHARGER board" at 2312.99,610.24 h39.37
